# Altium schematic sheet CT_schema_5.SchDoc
size 357 x 184 mm
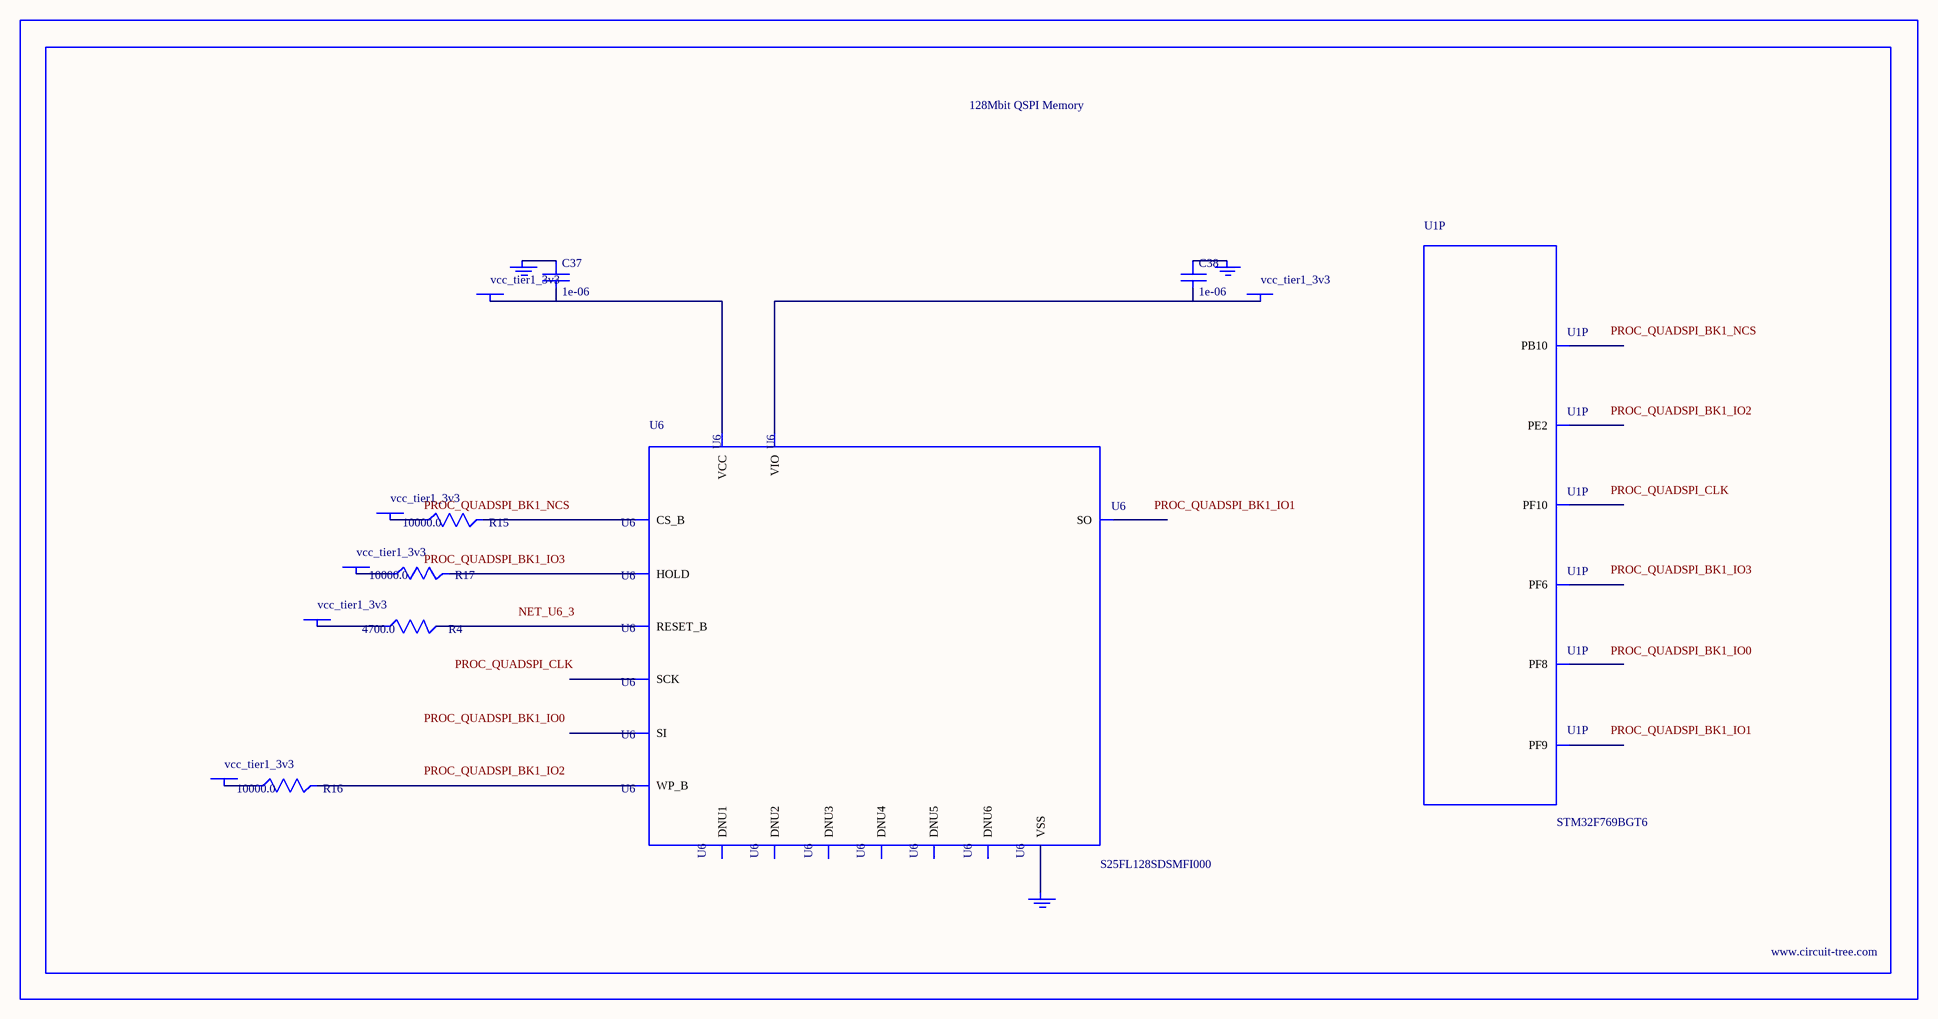
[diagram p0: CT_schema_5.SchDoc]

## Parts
BORDER4  (no value)
C37  1e-06  [C0603]
C38  1e-06  [C0603]
GND_INSTANCE_4_0  (no value)
GND_INSTANCE_4_1  (no value)
GND_INSTANCE_4_2  (no value)
POWER_INSTANCE_4_0  vcc_tier1_3v3
POWER_INSTANCE_4_1  vcc_tier1_3v3
POWER_INSTANCE_4_2  vcc_tier1_3v3
POWER_INSTANCE_4_3  vcc_tier1_3v3
POWER_INSTANCE_4_4  vcc_tier1_3v3
POWER_INSTANCE_4_5  vcc_tier1_3v3
R4  4700.0  [R0603]
R15  10000.0  [R0603]
R16  10000.0  [R0603]
R17  10000.0  [R0603]
U1  STM32F769BGT6  [LQFP208]  (part P of 17)
U6  S25FL128SDSMFI000  [S25FL128SDSMFI000]

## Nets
NetC37_1: C37.1 GND_INSTANCE_4_0.0(GND)
NetC37_2: C37.2 POWER_INSTANCE_4_1.0(PWR) U6.2(VCC)
NetC38_1: C38.1 GND_INSTANCE_4_1.0(GND)
NetC38_2: C38.2 POWER_INSTANCE_4_4.0(PWR) U6.14(VIO)
NetGND_INSTANCE_4_2_0: GND_INSTANCE_4_2.0(GND) U6.10(VSS)
NetPOWER_INSTANCE_4_0_0: POWER_INSTANCE_4_0.0(PWR) R17.1
NetPOWER_INSTANCE_4_2_0: POWER_INSTANCE_4_2.0(PWR) R15.1
NetPOWER_INSTANCE_4_3_0: POWER_INSTANCE_4_3.0(PWR) R16.1
NetPOWER_INSTANCE_4_5_0: POWER_INSTANCE_4_5.0(PWR) R4.1
NetR4_2: R4.2 U6.3(RESET_B)
NetR15_2: R15.2 U6.7(CS_B)
NetR16_2: R16.2 U6.9(WP_B)
NetR17_2: R17.2 U6.1(HOLD)

Not connected (* = marked no-connect by the designer): U1 1(PE2) 27(PF6) 29(PF8) 30(PF9) 31(PF10) 90(PB10); U6 4(DNU1) 5(DNU2) 6(DNU6) 8(SO) 11(DNU3) 12(DNU4) 13(DNU5) 15(SI) 16(SCK)

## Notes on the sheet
- Labels drawn without touching a wire or pin: NET_U6_3, PROC_QUADSPI_BK1_IO0, PROC_QUADSPI_BK1_IO1, PROC_QUADSPI_BK1_IO2, PROC_QUADSPI_BK1_IO3, PROC_QUADSPI_BK1_NCS, PROC_QUADSPI_CLK

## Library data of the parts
BORDER4 = BORDER_PAGE4
C37 C38 = C0603C105K3RACTU
GND_INSTANCE_4_0-GND_INSTANCE_4_2 = GND
POWER_INSTANCE_4_0-POWER_INSTANCE_4_5 = PWR
R4 = RC0603JR-074K7L
R15-R17 = RC0603JR-0710KL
